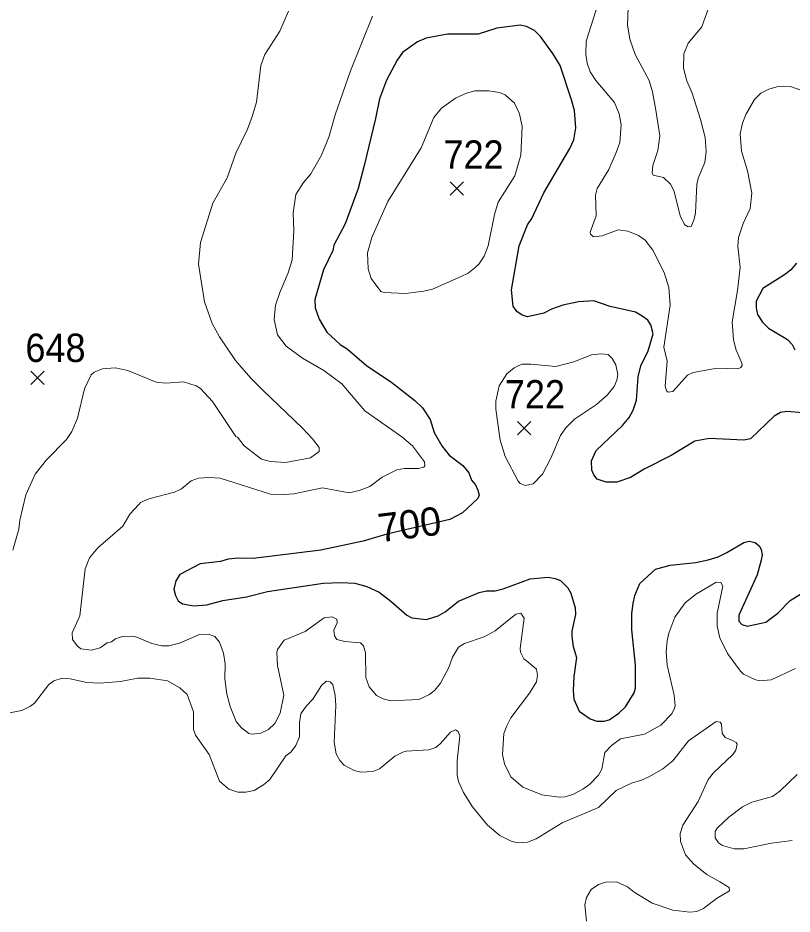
# Model space of a CAD drawing. Extents: x 294.2 to 320.3, y 7482.7 to 7510.7.
# Drawn here: x 315.257 to 317.439, y 7505.662 to 7508.188 of the extents above; entities that cross this region are included whole.
import ezdxf
from ezdxf.enums import TextEntityAlignment as Align

# ---------------------------------------------------------------- set-up
doc = ezdxf.new("R2010")
doc.units = 0
doc.header["$LTSCALE"] = 0.032
for name, color, linetype, lineweight in [('1', 7, 'Continuous', 25), ('2', 7, 'Continuous', 13), ('21', 7, 'Continuous', 25)]:
    doc.layers.add(name, color=color, linetype=linetype, lineweight=lineweight)
doc.layers.add('61', color=7, linetype='Continuous')

msp = doc.modelspace()

# ---------------------------------------------------------------- linework, layer by layer
at = {"layer": '1'}
for points in [[(316.9803, 7507.0617), (316.9911, 7507.0818), (317.0011, 7507.1108), (317.0055, 7507.1759), (317.0133, 7507.2076), (317.0333, 7507.2496), (317.0482, 7507.297), (317.0415, 7507.3223), (317.0332, 7507.3357), (317.0172, 7507.3475), (316.9977, 7507.3583), (316.9268, 7507.3745), (316.8807, 7507.3906), (316.8374, 7507.3873), (316.7936, 7507.3782), (316.7609, 7507.3669), (316.7393, 7507.3556), (316.6932, 7507.3454), (316.6783, 7507.3502), (316.6633, 7507.3599), (316.6528, 7507.3755), (316.6484, 7507.4212), (316.6705, 7507.5454), (316.6938, 7507.6046), (316.706, 7507.6229), (316.7392, 7507.6949), (316.813, 7507.8197), (316.8244, 7507.8444), (316.8296, 7507.8783), (316.8261, 7507.9271), (316.818, 7507.9574), (316.7853, 7508.0537), (316.7653, 7508.0881), (316.7298, 7508.1359), (316.7137, 7508.1521), (316.691, 7508.1639), (316.6727, 7508.1672), (316.6073, 7508.1591), (316.5546, 7508.1419), (316.4682, 7508.1425), (316.4082, 7508.1306), (316.3832, 7508.1209), (316.3411, 7508.0903), (316.3266, 7508.0693), (316.2962, 7508.0123), (316.2762, 7507.9601), (316.2656, 7507.9042), (316.2333, 7507.7719), (316.2159, 7507.7069), (316.1796, 7507.6079), (316.148, 7507.5477), (316.1446, 7507.5321), (316.1185, 7507.4781), (316.0941, 7507.3942), (316.0952, 7507.3711), (316.1068, 7507.3383), (316.1279, 7507.3017), (316.1651, 7507.2673), (316.1851, 7507.2549), (316.2394, 7507.2081), (316.3115, 7507.1597), (316.3764, 7507.1097), (316.3975, 7507.0887), (316.4197, 7507.0554), (316.4302, 7507.0193), (316.4518, 7506.9812), (316.4729, 7506.9554), (316.5117, 7506.9258), (316.5278, 7506.9059), (316.5361, 7506.8849), (316.5472, 7506.8715), (316.5539, 7506.857), (316.5572, 7506.8425), (316.5539, 7506.8328), (316.5106, 7506.7925), (316.4746, 7506.7741), (316.2972, 7506.7327), (316.2306, 7506.7133), (316.1114, 7506.687), (315.9201, 7506.6638), (315.8785, 7506.6649), (315.8502, 7506.6622), (315.8286, 7506.6558), (315.7709, 7506.6487), (315.7132, 7506.6186), (315.7027, 7506.6014), (315.6966, 7506.5777), (315.701, 7506.5594), (315.7088, 7506.5444), (315.721, 7506.5358), (315.7532, 7506.5304), (315.7897, 7506.5331), (315.8352, 7506.5455), (315.9017, 7506.5557), (315.9609, 7506.5707)], [(317.4514, 7507.4963), (317.4359, 7507.4775), (317.4209, 7507.4651), (317.3566, 7507.4248), (317.3377, 7507.3894), (317.3383, 7507.3705), (317.3416, 7507.3522), (317.356, 7507.3302), (317.3732, 7507.313), (317.4265, 7507.2812), (317.4393, 7507.2673), (317.447, 7507.252)], [(317.47, 7507.0742), (317.4245, 7507.0785), (317.4068, 7507.0753), (317.3885, 7507.0651), (317.3224, 7507.0009), (317.3035, 7506.9977), (317.207, 7507.0026), (317.1654, 7506.9945), (317.0988, 7506.9547), (317.0228, 7506.9159), (316.9835, 7506.8923), (316.9458, 7506.8793), (316.9158, 7506.8793), (316.8903, 7506.8874)], [(316.8903, 7506.8874), (316.8803, 7506.8998), (316.8747, 7506.9127), (316.8736, 7506.9391), (316.8872, 7506.9687), (316.9611, 7507.0393), (316.9803, 7507.0617)], [(316.3086, 7506.5433), (316.3535, 7506.5046), (316.3674, 7506.4971), (316.409, 7506.4917), (316.4422, 7506.5025), (316.4611, 7506.5132), (316.4988, 7506.5438), (316.5571, 7506.5681), (316.5782, 7506.5724), (316.6026, 7506.5724), (316.6248, 7506.5783), (316.7008, 7506.6069), (316.7518, 7506.6112), (316.7717, 7506.6079), (316.7862, 7506.6015), (316.8072, 7506.5811), (316.8161, 7506.566), (316.8277, 7506.5252), (316.8289, 7506.5057), (316.8187, 7506.4587), (316.8183, 7506.444), (316.8222, 7506.416), (316.8316, 7506.3848), (316.8244, 7506.3316), (316.8222, 7506.2923), (316.8245, 7506.2676), (316.8394, 7506.2332), (316.8699, 7506.2117), (316.8888, 7506.2052), (316.9093, 7506.2052), (316.9237, 7506.209), (316.9514, 7506.2278), (316.9697, 7506.2455), (316.9942, 7506.2854), (316.9981, 7506.2988), (316.9981, 7506.3628), (316.9875, 7506.4628), (316.9875, 7506.5085), (316.9914, 7506.537), (316.9958, 7506.5601), (317.0102, 7506.5935), (317.0546, 7506.6337), (317.0956, 7506.6456), (317.1683, 7506.6525), (317.2032, 7506.66), (317.2309, 7506.6686), (317.2553, 7506.6805), (317.303, 7506.7095), (317.3186, 7506.7132), (317.3352, 7506.7089), (317.3463, 7506.6998), (317.3519, 7506.6896), (317.3552, 7506.674), (317.3525, 7506.6595), (317.3411, 7506.6178), (317.289, 7506.5043), (317.289, 7506.4877), (317.2979, 7506.478), (317.3129, 7506.4731), (317.365, 7506.4844), (317.3994, 7506.5102), (317.4343, 7506.5452), (317.4659, 7506.5657)], [(315.9609, 7506.5707), (316.1173, 7506.5949), (316.1683, 7506.5966), (316.2066, 7506.5944), (316.2404, 7506.5847), (316.2759, 7506.5691), (316.3086, 7506.5433)]]:
    msp.add_lwpolyline(points, dxfattribs=at)
at = {"layer": '2'}
for points in [[(317.205, 7508.2186), (317.1846, 7508.1625), (317.1463, 7508.1171), (317.1341, 7508.0871), (317.1335, 7508.0463), (317.1424, 7508.0105), (317.1577, 7507.9754), (317.1814, 7507.902), (317.1942, 7507.8509), (317.1973, 7507.8113), (317.1935, 7507.7806), (317.175, 7507.7366), (317.1705, 7507.7181), (317.1667, 7507.6389), (317.1635, 7507.621), (317.1545, 7507.6), (317.1463, 7507.5987), (317.1373, 7507.6044), (317.1245, 7507.6274), (317.1061, 7507.7015), (317.0971, 7507.7194), (317.0767, 7507.7379), (317.0479, 7507.7449), (317.0448, 7507.7513), (317.0466, 7507.7717), (317.0607, 7507.8138), (317.0665, 7507.856), (317.0556, 7507.9275), (317.046, 7507.9799), (317.0364, 7508.0118), (316.9975, 7508.0846), (316.9822, 7508.128), (316.9758, 7508.1688), (316.9802, 7508.2908)], [(317.2969, 7507.8126), (317.3135, 7507.7564), (317.3263, 7507.6938), (317.3212, 7507.6504), (317.3014, 7507.6083), (317.2886, 7507.5687), (317.2867, 7507.5444), (317.2931, 7507.4844), (317.2854, 7507.4193), (317.2701, 7507.3312), (317.2739, 7507.2814), (317.281, 7507.2545), (317.2982, 7507.215), (317.2989, 7507.2085), (317.295, 7507.2021), (317.2867, 7507.199), (317.228, 7507.2009), (317.1603, 7507.1881), (317.1443, 7507.1804), (317.1028, 7507.1345), (317.0901, 7507.1326), (317.0856, 7507.1364), (317.0818, 7507.1498), (317.0869, 7507.2201), (317.078, 7507.2597), (317.0958, 7507.3784), (317.092, 7507.4282), (317.0792, 7507.4703), (317.0466, 7507.5329), (317.0249, 7507.561), (317.0064, 7507.5744), (316.9764, 7507.5865), (316.9496, 7507.5903), (316.9043, 7507.5737), (316.8794, 7507.5706), (316.8711, 7507.5782), (316.8698, 7507.584), (316.887, 7507.63), (316.8857, 7507.6887), (316.8896, 7507.7066), (316.9228, 7507.7608), (316.9439, 7507.8087), (316.9534, 7507.8368), (316.9573, 7507.8866), (316.9521, 7507.9173), (316.9388, 7507.9492), (316.8864, 7508.0111), (316.8704, 7508.036), (316.8615, 7508.0603), (316.8576, 7508.0858), (316.8589, 7508.1222), (316.8928, 7508.2289)], [(317.5204, 7508.2301), (317.5587, 7508.0692), (317.5676, 7508.0054), (317.5645, 7507.9696), (317.5472, 7507.9128), (317.5383, 7507.9051), (317.5306, 7507.9045), (317.5236, 7507.9083), (317.4859, 7507.9664), (317.4636, 7507.9843), (317.4374, 7507.9939), (317.4144, 7507.9951), (317.3966, 7507.9939), (317.3736, 7507.9869)], [(316.02, 7508.2071), (315.9951, 7508.1509), (315.953, 7508.0846), (315.9421, 7508.0539), (315.93, 7507.9505), (315.9178, 7507.9096), (315.9044, 7507.8739), (315.8718, 7507.8062), (315.847, 7507.7372), (315.8067, 7507.6657), (315.7722, 7507.5546), (315.7658, 7507.4933), (315.7831, 7507.3873), (315.8048, 7507.3261), (315.8259, 7507.289), (315.8706, 7507.2226)], [(316.2569, 7508.1931), (316.1943, 7508.0386), (316.1515, 7507.9147), (316.1343, 7507.8547), (316.1126, 7507.8011), (316.0826, 7507.7481), (316.0621, 7507.7244), (316.041, 7507.6906), (316.0327, 7507.6389), (316.0353, 7507.5878), (316.0302, 7507.5061), (316.0194, 7507.4691), (315.9951, 7507.4142), (315.9836, 7507.3784), (315.9791, 7507.3375), (315.9893, 7507.2941), (316.013, 7507.2622), (316.0596, 7507.229), (316.1196, 7507.1939), (316.17, 7507.1562), (316.2352, 7507.0802), (316.3398, 7507.0068), (316.3699, 7506.9819), (316.4037, 7506.9366), (316.4043, 7506.9257), (316.4011, 7506.9219)], [(317.3736, 7507.9869), (317.3512, 7507.9754), (317.3333, 7507.9575), (317.3091, 7507.916), (317.2995, 7507.8917), (317.2931, 7507.8611), (317.2969, 7507.8126)], [(316.1062, 7506.9653), (316.082, 7506.9482), (316.0111, 7506.9347), (315.9688, 7506.9374), (315.9441, 7506.9436), (315.8953, 7506.982), (315.8763, 7507.0062), (315.8712, 7507.0081), (315.8061, 7507.1064), (315.7722, 7507.1428), (315.7601, 7507.1511), (315.7238, 7507.162), (315.674, 7507.1581), (315.6465, 7507.1613), (315.5667, 7507.1939), (315.5309, 7507.2015), (315.4952, 7507.199), (315.4722, 7507.1894), (315.4639, 7507.1817), (315.4453, 7507.1422), (315.4256, 7507.0592), (315.409, 7507.0221), (315.3937, 7506.9992), (315.3381, 7506.9423), (315.3061, 7506.9021), (315.28, 7506.8434), (315.2627, 7506.7719), (315.2602, 7506.7463), (315.243, 7506.6876)], [(315.8706, 7507.2226), (315.914, 7507.1721), (315.9472, 7507.139), (316.0595, 7507.0317), (316.0877, 7507.0017), (316.1062, 7506.9768), (316.1062, 7506.9653)], [(316.4011, 7506.9219), (316.3865, 7506.9181), (316.3456, 7506.9181), (316.3252, 7506.9142), (316.2843, 7506.8931), (316.2492, 7506.8669), (316.2192, 7506.8555)], [(316.2192, 7506.8555), (316.1911, 7506.8491), (316.1158, 7506.8631), (316.0353, 7506.8465), (316.0085, 7506.844), (315.9689, 7506.8453), (315.8272, 7506.89), (315.7965, 7506.8925), (315.7659, 7506.89), (315.7455, 7506.8829), (315.718, 7506.8606), (315.6982, 7506.851), (315.6267, 7506.8325), (315.6024, 7506.8216), (315.598, 7506.8165), (315.573, 7506.7885), (315.5526, 7506.7553), (315.4824, 7506.6939), (315.4588, 7506.6659), (315.4466, 7506.6352), (315.4313, 7506.5024), (315.4105, 7506.4542), (315.4111, 7506.4353), (315.4243, 7506.4175), (315.4341, 7506.4097), (315.4645, 7506.4052), (315.4886, 7506.4124), (315.5087, 7506.4264), (315.5208, 7506.4291), (315.5323, 7506.4375), (315.5512, 7506.4445), (315.5807, 7506.4449), (315.5928, 7506.4424), (315.6344, 7506.4239), (315.6625, 7506.4181), (315.6829, 7506.4175), (315.7123, 7506.4252), (315.769, 7506.4494), (315.7948, 7506.4507), (315.8126, 7506.4441), (315.8252, 7506.4285), (315.8367, 7506.3967), (315.8413, 7506.3667), (315.8407, 7506.3252), (315.8457, 7506.2815), (315.8552, 7506.247), (315.8725, 7506.2049), (315.8878, 7506.187), (315.9082, 7506.1704), (315.9166, 7506.1685), (315.9421, 7506.1716), (315.9638, 7506.1819), (315.9811, 7506.1991), (315.9964, 7506.2279), (316.0072, 7506.2783), (315.9893, 7506.362), (315.9868, 7506.399), (315.9887, 7506.4073), (316.0079, 7506.4334), (316.0671, 7506.4581), (316.1208, 7506.4966), (316.1426, 7506.4992), (316.156, 7506.4928), (316.1573, 7506.4826), (316.1477, 7506.4616), (316.1496, 7506.4462), (316.1566, 7506.436), (316.1784, 7506.4303), (316.223, 7506.4258), (316.2313, 7506.4175), (316.237, 7506.3977), (316.2383, 7506.3281), (316.2473, 7506.3019), (316.2677, 7506.2776), (316.2869, 7506.2681), (316.3073, 7506.263), (316.387, 7506.2669), (316.4174, 7506.2808), (316.4323, 7506.2931), (316.4484, 7506.3126), (316.4714, 7506.3571), (316.4823, 7506.3858), (316.4995, 7506.4142), (316.5156, 7506.4242), (316.5713, 7506.4431), (316.6023, 7506.4602), (316.661, 7506.5069), (316.6744, 7506.51), (316.684, 7506.496), (316.6725, 7506.4105), (316.6738, 7506.4003), (316.6834, 7506.3811), (316.6955, 7506.3715), (316.7191, 7506.3517), (316.7217, 7506.3351)], [(316.6234, 7506.1117), (316.6285, 7506.0849), (316.647, 7506.0484), (316.6802, 7506.0197), (316.7338, 7505.998), (316.7824, 7505.9916), (316.8002, 7505.9922), (316.8232, 7505.9993), (316.8494, 7506.0133), (316.8692, 7506.028), (316.8941, 7506.0531), (316.9033, 7506.0704), (316.9119, 7506.1166), (316.9303, 7506.1369), (316.9555, 7506.1559), (317.0238, 7506.1692), (317.0692, 7506.1945), (317.1002, 7506.2263), (317.1079, 7506.2419), (317.1099, 7506.2483), (317.1073, 7506.279), (317.0875, 7506.3632), (317.0849, 7506.4003), (317.0869, 7506.4315), (317.092, 7506.4539), (317.1086, 7506.4986), (317.138, 7506.5394), (317.1673, 7506.5624), (317.2255, 7506.5975), (317.2382, 7506.5967), (317.2445, 7506.5856), (317.2284, 7506.5098), (317.2278, 7506.4729), (317.2353, 7506.44), (317.2573, 7506.3964), (317.2938, 7506.3466), (317.302, 7506.3376), (317.334, 7506.323), (317.3467, 7506.3192), (317.3806, 7506.3217), (317.4489, 7506.3543)], [(315.2334, 7506.2291), (315.2679, 7506.2355), (315.2927, 7506.2477), (315.3036, 7506.2566), (315.3445, 7506.3089), (315.3585, 7506.3192), (315.3815, 7506.3262), (315.4045, 7506.3243), (315.4518, 7506.3141), (315.4875, 7506.3121), (315.5463, 7506.3172), (315.5948, 7506.3262), (315.6293, 7506.3268), (315.6791, 7506.3192), (315.7135, 7506.2994), (315.7346, 7506.2809), (315.7525, 7506.2317), (315.7525, 7506.1819), (315.7582, 7506.1659), (315.7965, 7506.1117), (315.8259, 7506.0363), (315.8521, 7506.0133), (315.877, 7506.0056), (315.9, 7506.0056), (315.923, 7506.0101), (315.9498, 7506.0261), (315.9677, 7506.0414), (316.0123, 7506.1078), (316.027, 7506.1193), (316.0404, 7506.1372), (316.0506, 7506.1615), (316.0513, 7506.2011), (316.0551, 7506.2259), (316.0698, 7506.2476), (316.0889, 7506.2675), (316.1132, 7506.3058), (316.126, 7506.3179), (316.1375, 7506.3166), (316.1451, 7506.3089), (316.1515, 7506.2777), (316.1533, 7506.2494), (316.1489, 7506.1461), (316.1547, 7506.1129), (316.1645, 7506.0943), (316.1771, 7506.0809), (316.2047, 7506.0665), (316.2237, 7506.0614), (316.2575, 7506.0631), (316.2765, 7506.0712), (316.3194, 7506.1065), (316.3418, 7506.118), (316.352, 7506.1212), (316.4152, 7506.125), (316.4348, 7506.1315), (316.4474, 7506.1415), (316.4767, 7506.1743), (316.4905, 7506.1805)], [(316.7217, 7506.3351), (316.7191, 7506.316), (316.6993, 7506.2841), (316.6463, 7506.2151), (316.6349, 7506.1921), (316.6272, 7506.1704), (316.6234, 7506.1117)], [(316.5129, 7506.0044), (316.539, 7505.9642), (316.5806, 7505.9125), (316.6157, 7505.8828), (316.6479, 7505.8667), (316.6657, 7505.8622), (316.6932, 7505.8645), (316.7179, 7505.8737), (316.7912, 7505.9188), (316.894, 7505.9622), (316.9439, 7506.0095), (316.9867, 7506.0306), (317.0148, 7506.0389), (317.0377, 7506.0497), (317.0748, 7506.0714), (317.1028, 7506.0937), (317.1475, 7506.15), (317.2255, 7506.2042), (317.2369, 7506.2023), (317.2407, 7506.1972), (317.2427, 7506.1717), (317.2509, 7506.1589), (317.2714, 7506.1512), (317.2816, 7506.1455), (317.2842, 7506.1404), (317.281, 7506.1232), (317.272, 7506.111), (317.2178, 7506.0599), (317.2031, 7506.0408), (317.175, 7505.9789), (317.1317, 7505.912), (317.1243, 7505.8886), (317.1252, 7505.8665), (317.1386, 7505.8282), (317.1629, 7505.802), (317.1992, 7505.7732), (317.2357, 7505.7522), (317.2618, 7505.7368), (317.2631, 7505.7273), (317.2267, 7505.7056), (317.1897, 7505.6775), (317.1705, 7505.6692), (317.1514, 7505.6666), (317.1029, 7505.6724), (317.0454, 7505.6922), (316.9943, 7505.7234), (316.9758, 7505.7381), (316.9445, 7505.7522), (316.9139, 7505.7515), (316.8934, 7505.7445), (316.873, 7505.7311), (316.8597, 7505.708), (316.8551, 7505.6874), (316.8596, 7505.6418)], [(316.4905, 7506.1805), (316.4979, 7506.176), (316.5025, 7506.1638), (316.495, 7506.0938), (316.495, 7506.0529), (316.4988, 7506.035), (316.5129, 7506.0044)], [(317.4534, 7506.0548), (317.4049, 7506.0082), (317.3838, 7505.9929), (317.3263, 7505.9775), (317.2995, 7505.9642), (317.2612, 7505.9348), (317.2286, 7505.9041), (317.2229, 7505.8946), (317.2223, 7505.8767), (317.2318, 7505.8626), (317.2433, 7505.855), (317.2765, 7505.8454), (317.3033, 7505.8454), (317.3812, 7505.8614), (317.44, 7505.869)]]:
    msp.add_lwpolyline(points, dxfattribs=at)
for points in [[(316.5065, 7507.4594), (316.4261, 7507.4237), (316.4018, 7507.4173), (316.3495, 7507.411), (316.2894, 7507.4135), (316.2798, 7507.4167), (316.253, 7507.4531), (316.2441, 7507.4806), (316.2428, 7507.5253), (316.2549, 7507.5687), (316.2996, 7507.6708), (316.3935, 7507.8215), (316.4299, 7507.907), (316.4516, 7507.9332), (316.4905, 7507.9613), (316.5219, 7507.976), (316.5448, 7507.9824), (316.5844, 7507.9824), (316.6144, 7507.9779), (316.6304, 7507.9715), (316.6566, 7507.9473), (316.6706, 7507.9173), (316.6783, 7507.8815), (316.675, 7507.8011), (316.6578, 7507.7423), (316.6112, 7507.6683), (316.6004, 7507.6338), (316.5831, 7507.5457), (316.5716, 7507.5163), (316.5563, 7507.4933), (316.5448, 7507.4831), (316.5263, 7507.4684)], [(316.7032, 7507.2117), (316.6789, 7507.2118), (316.6674, 7507.2072), (316.6559, 7507.2015), (316.6355, 7507.1843), (316.6137, 7507.1511), (316.6048, 7507.1077), (316.6042, 7507.0847), (316.617, 7506.9979), (316.631, 7506.9519), (316.6674, 7506.8817), (316.6732, 7506.8752), (316.6872, 7506.8695), (316.7095, 7506.8746), (316.7357, 7506.9021), (316.7593, 7506.9468), (316.7868, 7507.0106), (316.8015, 7507.0324), (316.8264, 7507.0572), (316.8883, 7507.0981), (316.9183, 7507.1249), (316.9375, 7507.1485), (316.9452, 7507.1664), (316.9483, 7507.183), (316.9426, 7507.2098), (316.9324, 7507.2277), (316.9209, 7507.2392), (316.9011, 7507.2405), (316.8743, 7507.2386), (316.8245, 7507.2181), (316.7734, 7507.2054)]]:
    msp.add_lwpolyline(points, close=True, dxfattribs=at)
at = {"layer": '21'}
for p, q in [((316.4758, 7507.7256), (316.5133, 7507.6881)), ((316.5133, 7507.7256), (316.4758, 7507.6881)), ((315.2935, 7507.192), (315.331, 7507.1545)), ((315.331, 7507.192), (315.2935, 7507.1545)), ((316.6654, 7507.0503), (316.7029, 7507.0128)), ((316.7029, 7507.0503), (316.6654, 7507.0128))]:
    msp.add_line(p, q, dxfattribs=at)

# ---------------------------------------------------------------- texts
at = {"layer": '61', "width": 0.95}
for s, p in [('722', (316.5414, 7507.7627)), ('648', (315.3631, 7507.218)), ('722', (316.7145, 7507.0869))]:
    msp.add_text(s, height=0.08, dxfattribs=at).set_placement(p, align=Align.CENTER)
at = {"layer": '61'}
msp.add_text('700', height=0.08, rotation=7.165, dxfattribs=at).set_placement((316.3661, 7506.7208), align=Align.CENTER)

doc.saveas('drawing.dxf')
